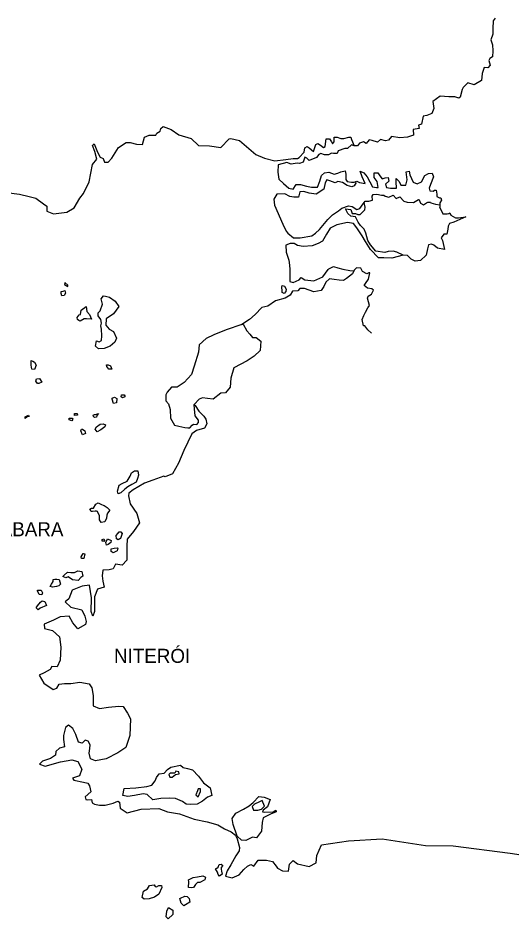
# Model space of a CAD drawing. Extents: x 662444 to 1640468, y 7452018 to 9606170.
# Drawn here: x 690454 to 712609, y 7455211 to 7495631 of the extents above; entities that cross this region are included whole.
import ezdxf

# ---------------------------------------------------------------- set-up
doc = ezdxf.new("R2010")
doc.units = 0
doc.layers.add('Level 1', color=7, linetype='Continuous')
doc.layers.add('Level 3', color=7, linetype='Continuous')

msp = doc.modelspace()

# ---------------------------------------------------------------- linework, layer by layer
at = {"layer": 'Level 1'}
for points in [[(711848, 7495631), (711764, 7495510), (711749, 7495167), (711746, 7494902), (711660, 7494648), (711729, 7494425), (711756, 7494159), (711732, 7493894), (711618, 7493818), (711565, 7493730), (711624, 7493519), (711529, 7493398), (711355, 7493412), (711279, 7493136), (711244, 7492826), (710912, 7492631), (710626, 7492724), (710417, 7492516), (710375, 7492428), (710278, 7492086), (710226, 7492031), (710052, 7492089), (709784, 7492093), (709384, 7492132), (709052, 7491892), (709109, 7491570), (709013, 7491350), (708786, 7491265), (708621, 7491223), (708544, 7490869), (708420, 7490827), (708439, 7490682), (708181, 7490631), (708198, 7490376), (707930, 7490291), (707580, 7490251), (707200, 7490323), (707065, 7490158), (706941, 7490116), (706705, 7490174), (706570, 7490065), (706345, 7490135), (706201, 7490170), (706076, 7489995), (705943, 7490074), (705768, 7490021), (705684, 7489900), (705530, 7489891), (705407, 7489948), (705230, 7489773), (705107, 7489775), (704817, 7489679), (704764, 7489558), (704610, 7489560), (704518, 7489561), (704383, 7489497), (704198, 7489499), (704035, 7489557), (703952, 7489514), (703837, 7489371), (703506, 7489243), (703405, 7489344), (703313, 7489389), (703248, 7489157), (703073, 7489104), (702980, 7489117)], [(689932, 7487801), (690527, 7487727), (690958, 7487622), (691255, 7487552), (691591, 7487293), (691744, 7487191), (691751, 7486969), (692047, 7486844), (692644, 7486925), (692976, 7487109), (693228, 7487549), (693395, 7487757), (693648, 7488286), (693802, 7489059), (693990, 7489300), (693902, 7489645), (693792, 7489912), (693875, 7489988), (694025, 7489610), (694135, 7489387), (694268, 7489330), (694338, 7489163), (694492, 7489161), (694659, 7489347), (694963, 7489819), (695305, 7490048), (695490, 7490045), (695766, 7489975), (696033, 7489961), (696120, 7490292), (696337, 7490378), (696635, 7490374), (696687, 7490462), (696833, 7490560), (696855, 7490670), (696958, 7490757), (697327, 7490631), (697663, 7490394), (698226, 7490220), (698551, 7489906), (699044, 7489900), (699557, 7489826), (699922, 7490209), (699994, 7490219), (700383, 7490137), (701125, 7489507), (701514, 7489347), (701975, 7489219), (702469, 7489279), (702798, 7489330), (702983, 7489327)], [(702983, 7489327), (703066, 7489381), (703285, 7489611), (703319, 7489810), (703422, 7489864), (703514, 7489807), (703707, 7489639), (703814, 7489958), (703907, 7490002), (704019, 7489934), (704151, 7489821), (704234, 7489864), (704270, 7490218), (704321, 7490218), (704424, 7490216), (704515, 7490082), (704554, 7489982), (704638, 7490080), (704641, 7490291), (704774, 7490289), (704938, 7490220), (705071, 7490219), (705288, 7490282), (705381, 7490281), (705410, 7490181), (705530, 7489891)], [(702980, 7489117), (702702, 7489076), (702508, 7489156), (702116, 7489040), (702102, 7488719), (702159, 7488397), (702362, 7488206), (702606, 7487992)], [(702606, 7487992), (702801, 7487956), (702927, 7488165), (703122, 7488162), (703398, 7488092), (703624, 7488045), (703891, 7488041), (703987, 7488306), (704062, 7488560), (704198, 7488691), (704393, 7488721), (704639, 7488629), (704804, 7488671), (704938, 7488736), (705124, 7488778), (705163, 7488633), (705160, 7488390), (705220, 7488300), (705405, 7488265), (705538, 7488263), (705652, 7488306), (705764, 7488249), (706021, 7488201), (705891, 7488513), (705802, 7488758), (705966, 7488689), (706117, 7488510), (706227, 7488287), (706358, 7488063), (706532, 7488028), (706614, 7488027), (706556, 7488304), (706425, 7488483), (706428, 7488683), (706592, 7488681), (706683, 7488546), (706794, 7488423), (706928, 7488454), (707052, 7488475), (707081, 7488308), (706935, 7488177), (706984, 7488033), (707159, 7487997), (707426, 7488005), (707419, 7488282), (707421, 7488426), (707553, 7488302), (707623, 7488135), (707849, 7488132), (707914, 7488375), (707867, 7488730), (707991, 7488761), (708030, 7488595), (708180, 7488260), (708353, 7488191), (708550, 7488277), (708698, 7488563), (708863, 7488650), (709028, 7488669), (709087, 7488503), (708959, 7488161), (708895, 7487996), (708925, 7487873), (709079, 7487860), (709141, 7487915), (709213, 7487914), (709241, 7487736), (709240, 7487625), (709352, 7487568), (709414, 7487568), (709443, 7487456), (709380, 7487335), (709379, 7487247), (709377, 7487114), (709377, 7487125), (709507, 7486846), (709702, 7486844), (709774, 7486865), (709816, 7486897), (709865, 7486786), (710080, 7486672), (710203, 7486671), (710532, 7486710)], [(705620, 7488251), (705536, 7488108), (705423, 7488065), (705218, 7488123), (705004, 7488248), (704799, 7488295), (704685, 7488241), (704440, 7488322), (704307, 7488368), (704233, 7488236), (704167, 7487960), (703825, 7487732), (703517, 7487769), (703272, 7487850), (703097, 7487830), (703032, 7487599), (702830, 7487594), (702652, 7487626)], [(702652, 7487626), (702428, 7487740), (702058, 7487722), (701921, 7487503), (701959, 7487236), (702327, 7486378), (702488, 7486066), (702558, 7485977), (702812, 7485763)], [(702812, 7485763), (702792, 7485774), (703111, 7485770), (703636, 7485852), (703792, 7485982), (703979, 7486146), (704344, 7486595), (704563, 7486803), (704822, 7486988), (704978, 7487107), (705277, 7487203), (705441, 7487168), (705645, 7487043), (705790, 7487085), (705863, 7487195), (705978, 7487349), (706031, 7487414), (706195, 7487412), (706350, 7487454), (706332, 7487643), (706384, 7487720), (706549, 7487729), (706764, 7487681), (706856, 7487691), (706928, 7487635), (707081, 7487599), (707278, 7487685), (707420, 7487539), (707575, 7487604), (707757, 7487413), (707911, 7487367), (708188, 7487352), (708416, 7487482), (708446, 7487470), (708506, 7487325), (708639, 7487257), (708774, 7487344), (708835, 7487365), (708948, 7487364), (708969, 7487341), (709173, 7487283), (709379, 7487247)], [(710532, 7486710), (709995, 7486474), (709809, 7486410), (709746, 7486289), (709733, 7486156), (709689, 7485935), (709556, 7485937), (709430, 7485773), (709500, 7485650), (709587, 7485239), (709270, 7485299), (709097, 7485434), (709005, 7485480), (708871, 7485459), (708827, 7485283), (708762, 7484996), (708502, 7484756), (708265, 7484726), (708092, 7484817), (707919, 7484974), (707724, 7484999), (707438, 7485125), (707274, 7485171), (707058, 7485152), (706904, 7485110), (706504, 7485170), (706261, 7485462), (706140, 7485652), (706052, 7485985), (705973, 7486163), (705820, 7486321), (705710, 7486477), (705589, 7486711), (705374, 7486736), (705242, 7486860), (705142, 7487072), (705378, 7487035), (705448, 7486868), (705592, 7486866), (705694, 7486821), (705807, 7486819), (706015, 7487027), (706017, 7487149), (705978, 7487349)], [(707724, 7484999), (707219, 7484862), (706859, 7484867), (706623, 7484870), (706258, 7485251), (706037, 7485609), (705896, 7485854), (705836, 7485944), (705644, 7486212), (705503, 7486413), (705237, 7486461), (704752, 7486346), (704452, 7486206), (704284, 7485931), (704105, 7485624), (703909, 7485516), (703650, 7485408), (703239, 7485381), (702983, 7485428), (702840, 7485519)], [(702840, 7485519), (702655, 7485510), (702469, 7485435), (702485, 7485125), (702604, 7484769), (702632, 7484547), (702639, 7484347), (702646, 7484059), (702644, 7483937), (702643, 7483805), (702796, 7483769)], [(706310, 7481496), (706148, 7481642), (706006, 7481821), (705945, 7481822), (705887, 7482111), (705971, 7482287), (706035, 7482430), (706140, 7482628), (706224, 7482737), (706126, 7483060), (706158, 7483148), (706313, 7483246), (706398, 7483422), (706327, 7483478), (706122, 7483514), (705979, 7483627), (706032, 7483726), (706168, 7483912), (706234, 7484199), (706193, 7484200), (706099, 7484157), (705906, 7484259), (705826, 7484415), (705641, 7484418), (705537, 7484320), (705452, 7484155), (705192, 7483948), (705058, 7483861), (704852, 7483864), (704637, 7483900), (704432, 7483936), (704255, 7483783), (704170, 7483585), (704055, 7483409), (703715, 7483347), (703296, 7483497), (703091, 7483500), (702997, 7483390), (702770, 7483371)], [(702796, 7483769), (703065, 7483888), (703159, 7483986), (703322, 7483884), (703722, 7483846), (704125, 7484017), (704366, 7484346), (704397, 7484379), (704604, 7484476), (704798, 7484429), (705024, 7484371), (705341, 7484300), (705495, 7484287)], [(692695, 7483646), (692553, 7483769), (692532, 7483681), (692695, 7483590), (692695, 7483646)], [(702290, 7483566), (702301, 7483632), (702403, 7483597), (702474, 7483463), (702472, 7483364), (702389, 7483276), (702297, 7483322), (702298, 7483377), (702290, 7483566)], [(702770, 7483371), (702655, 7483195), (702437, 7483065), (702004, 7482938), (701652, 7482710), (701394, 7482647), (701092, 7482330), (700832, 7482112), (700490, 7481884), (699789, 7481649), (699231, 7481424), (698900, 7481251), (698578, 7480967), (698543, 7480647), (698360, 7480018), (698242, 7479642), (697909, 7479281), (697588, 7479075), (697341, 7479067), (697143, 7478848), (697080, 7478727), (697077, 7478461), (697198, 7478316), (697277, 7478071), (697292, 7477672), (697473, 7477371), (697668, 7477313), (697934, 7477254), (698067, 7477241), (698160, 7477251), (698264, 7477361), (698326, 7477404), (698470, 7477402), (698553, 7477490), (698554, 7477589), (698403, 7477791), (698366, 7478101), (698357, 7478291), (698401, 7478243), (698560, 7477988), (698793, 7477774), (698873, 7477641), (698922, 7477418), (698817, 7477231), (698456, 7477125), (698249, 7476973), (697890, 7476225), (697646, 7475663), (697383, 7475179), (697053, 7475050), (696992, 7475073), (696507, 7474902), (696125, 7474763), (695618, 7474460), (695421, 7474318), (695409, 7474197), (695487, 7473841), (695779, 7473405), (695907, 7472983), (695635, 7472599), (695343, 7472248), (695339, 7471938), (695331, 7471307), (695123, 7471088), (694826, 7471136), (694720, 7470916), (694535, 7470874), (694258, 7470855), (694224, 7470612), (694262, 7470368), (694320, 7470101), (694021, 7470006), (693883, 7469664), (693878, 7469243), (693885, 7468999), (693810, 7468801), (693741, 7469012), (693749, 7469621), (693664, 7470187), (693325, 7470147), (692881, 7469965), (692732, 7469568), (692566, 7469437), (692820, 7469201), (693321, 7469073), (693451, 7468794), (693509, 7468550), (693487, 7468417), (693136, 7468234), (692913, 7468491), (692753, 7468792), (692342, 7468764), (692043, 7468624), (691620, 7468441), (691648, 7468242), (692006, 7468148), (692321, 7467867), (692376, 7467402), (692348, 7466826), (692211, 7466529), (691975, 7466532)], [(692549, 7483404), (692578, 7483282), (692525, 7483183), (692422, 7483162), (692383, 7483273), (692383, 7483340), (692384, 7483362), (692486, 7483372), (692549, 7483404)], [(694201, 7481666), (694172, 7481822), (694204, 7481943), (694165, 7482110), (694044, 7482277), (694046, 7482410), (694140, 7482498), (694246, 7482795), (694188, 7483040), (694282, 7483160), (694384, 7483148), (694558, 7483113), (694813, 7482932), (694974, 7482686), (694734, 7482357), (694402, 7482140), (694398, 7481852), (694540, 7481673), (694734, 7481560), (694874, 7481270), (694799, 7481083), (694592, 7480908), (694323, 7480801), (694066, 7480793), (693924, 7480906), (693968, 7481149), (694101, 7481103), (694205, 7481168), (694207, 7481367), (694201, 7481666)], [(693150, 7482256), (693192, 7482310), (693254, 7482332), (693287, 7482531), (693505, 7482683), (693543, 7482472), (693655, 7482327), (693745, 7482126), (693519, 7482140), (693416, 7482141), (693240, 7482033), (693179, 7482056), (693118, 7482112), (693109, 7482201), (693150, 7482256)], [(700490, 7481884), (700552, 7481894), (700713, 7481593), (700855, 7481447), (700976, 7481301), (701140, 7481299), (701344, 7481141), (701317, 7480710), (701047, 7480459), (700736, 7480252), (700136, 7479939), (699996, 7479476), (699971, 7479077), (699762, 7478814), (699546, 7478806), (699204, 7478533), (698947, 7478559), (698732, 7478584), (698577, 7478531), (698357, 7478291)], [(691048, 7480056), (691040, 7480266), (691112, 7480243), (691193, 7480187), (691263, 7480053), (691199, 7479855), (691076, 7479878), (691048, 7480056)], [(694601, 7480033), (694661, 7479877), (694527, 7479879), (694436, 7479991), (694427, 7480068), (694499, 7480079), (694601, 7480033)], [(691276, 7479444), (691420, 7479464), (691521, 7479297), (691386, 7479232), (691325, 7479233), (691254, 7479333), (691276, 7479444)], [(694878, 7478368), (694744, 7478337), (694674, 7478537), (694675, 7478581), (694788, 7478624), (694890, 7478556), (694878, 7478368)], [(695251, 7478629), (695147, 7478586), (695087, 7478642), (695088, 7478731), (695211, 7478729), (695251, 7478684), (695251, 7478629)], [(690947, 7477753), (690865, 7477743), (690781, 7477667), (690782, 7477744), (690917, 7477809), (690947, 7477753)], [(693125, 7477814), (692991, 7477805), (692982, 7477894), (692992, 7477894), (693105, 7477892), (693125, 7477814)], [(693987, 7477792), (693976, 7477726), (693883, 7477705), (693843, 7477761), (693823, 7477817), (693885, 7477849), (693936, 7477848), (694070, 7477891), (693987, 7477792)], [(692907, 7477629), (692875, 7477552), (692742, 7477598), (692743, 7477675), (692805, 7477686), (692877, 7477685), (692907, 7477629)], [(694350, 7477289), (694174, 7477159), (694009, 7477072), (693907, 7477184), (693970, 7477283), (694136, 7477403), (694280, 7477423), (694372, 7477378), (694350, 7477289)], [(693353, 7477180), (693444, 7477113), (693484, 7476990), (693339, 7476926), (693270, 7477115), (693301, 7477181), (693353, 7477180)], [(695809, 7474967), (695756, 7474812), (695560, 7474704), (695373, 7474596), (695249, 7474487), (695072, 7474323), (694948, 7474280), (694919, 7474402), (694994, 7474667), (695129, 7474743), (695356, 7474851), (695482, 7475071), (695546, 7475225), (695680, 7475323), (695824, 7475321), (695852, 7475121), (695809, 7474967)], [(694275, 7473779), (694315, 7473768), (694458, 7473666), (694569, 7473554), (694475, 7473422), (694443, 7473323), (694421, 7473190), (694347, 7473025), (694182, 7473005), (694112, 7473117), (694114, 7473294), (694024, 7473494), (693973, 7473506), (693912, 7473507), (693788, 7473497), (693737, 7473487), (693677, 7473599), (693749, 7473642), (693842, 7473641), (693947, 7473828), (694050, 7473882), (694193, 7473813), (694275, 7473779)], [(695025, 7472263), (694942, 7472220), (694871, 7472265), (694863, 7472420), (694925, 7472508), (694998, 7472574), (695060, 7472573), (695131, 7472506), (695046, 7472274), (695025, 7472263)], [(694305, 7472151), (694274, 7472162), (694233, 7472163), (694234, 7472240), (694296, 7472273), (694326, 7472184), (694305, 7472151)], [(694612, 7472102), (694498, 7472015), (694426, 7471983), (694397, 7472094), (694471, 7472270), (694634, 7472191), (694612, 7472102)], [(694895, 7471722), (694729, 7471636), (694628, 7471703), (694639, 7471814), (694773, 7471846), (694897, 7471855), (694927, 7471844), (694895, 7471722)], [(693402, 7471376), (693371, 7471376), (693299, 7471377), (693290, 7471455), (693374, 7471609), (693395, 7471609), (693446, 7471586), (693402, 7471376)], [(693268, 7470536), (693153, 7470393), (692897, 7470419), (692704, 7470565), (692601, 7470522), (692468, 7470579), (692520, 7470634), (692676, 7470765), (692829, 7470752), (692994, 7470761), (693138, 7470825), (693323, 7470801), (693361, 7470590), (693268, 7470536)], [(692278, 7470161), (692185, 7470129), (692000, 7470098), (691898, 7470132), (691961, 7470231), (692034, 7470352), (692035, 7470441), (692107, 7470462), (692199, 7470450), (692302, 7470448), (692361, 7470226), (692278, 7470161)], [(691523, 7469760), (691400, 7469762), (691331, 7469929), (691331, 7469962), (691495, 7469960), (691555, 7469838), (691523, 7469760)], [(691458, 7469418), (691530, 7469484), (691663, 7469460), (691733, 7469282), (691454, 7469152), (691351, 7469087), (691270, 7469177), (691322, 7469265), (691458, 7469418)], [(691975, 7466532), (691902, 7466400), (691633, 7466259), (691396, 7466151), (691606, 7465783), (692024, 7465501), (692189, 7465565), (692293, 7465741), (692540, 7465782), (692817, 7465779), (693228, 7465829), (693648, 7465757), (693759, 7465578), (693826, 7465234), (693820, 7464780), (694106, 7464655), (694517, 7464716), (694980, 7464765), (695174, 7464741), (695365, 7464439), (695495, 7464194), (695475, 7463441), (695294, 7462911), (694932, 7462661), (694405, 7462391), (693932, 7462309), (693707, 7462389), (693639, 7462645), (693673, 7462866), (693695, 7463021), (693605, 7463188), (693472, 7463234), (693337, 7463103), (693163, 7463138), (693044, 7463483), (692914, 7463751), (692722, 7463908), (692587, 7463799), (692490, 7463435), (692488, 7463269), (692535, 7462936), (692308, 7462872), (692152, 7462719), (692140, 7462564), (691912, 7462412), (691552, 7462284), (691417, 7462153), (691672, 7462061), (692362, 7462262), (692866, 7462345), (693142, 7462275), (693322, 7461929), (693205, 7461631), (692896, 7461525), (692957, 7461435), (693397, 7461352), (693581, 7461305), (693661, 7461183), (693719, 7460916), (693460, 7460698), (693489, 7460576), (693592, 7460563), (693756, 7460572), (693775, 7460428), (693887, 7460360), (694112, 7460324), (694358, 7460321), (694718, 7460405), (694924, 7460502), (695006, 7460456), (695033, 7460179), (695348, 7459976), (695976, 7460134), (696766, 7460168), (697165, 7460018), (697697, 7459923), (698360, 7459692), (698933, 7459563), (699414, 7459435), (699719, 7459254), (700015, 7459128), (700207, 7458970), (700277, 7458803), (700385, 7458414), (700373, 7458270), (700216, 7458051), (699995, 7457644), (699837, 7457369), (699762, 7457126), (700059, 7457056), (700368, 7457196), (700577, 7457426), (700743, 7457579), (700898, 7457654), (701030, 7457586), (701228, 7457849), (701598, 7457844), (701874, 7457785), (702025, 7457583), (702085, 7457494), (702319, 7457369)], [(697511, 7460623), (697244, 7460626), (696865, 7460609), (696505, 7460559), (696241, 7460795), (696067, 7460819), (695677, 7460758), (695378, 7460706), (695153, 7460753), (695219, 7461063), (695742, 7461089), (696236, 7461149), (696452, 7461213), (696608, 7461410), (696672, 7461564), (696787, 7461718), (697013, 7461759), (697159, 7461924), (697314, 7462021), (697746, 7462104), (697857, 7462003), (698052, 7461967), (698287, 7461909), (698550, 7461617), (698772, 7461315), (699076, 7461090), (699154, 7460745), (698958, 7460670), (698730, 7460496), (698492, 7460355), (698205, 7460348), (698000, 7460362), (697837, 7460475), (697511, 7460623)], [(697537, 7461841), (697485, 7461753), (697280, 7461756), (697217, 7461690), (697257, 7461568), (697369, 7461566), (697515, 7461697), (697689, 7461717), (697670, 7461806), (697537, 7461841)], [(698510, 7460953), (698436, 7460777), (698538, 7460698), (698643, 7460929), (698645, 7461051), (698532, 7461053), (698510, 7460953)], [(700666, 7458732), (700471, 7458745), (700289, 7458925), (700111, 7459448), (700053, 7459714), (700221, 7459956), (700562, 7460140), (700820, 7460280), (700996, 7460444), (701256, 7460706), (701492, 7460670), (701757, 7460578), (701650, 7460236), (701443, 7460095), (701422, 7460017), (701493, 7460005), (701904, 7460022), (702017, 7460087), (702037, 7460020), (701779, 7459913), (701449, 7459751), (701405, 7459541), (701379, 7459154), (701149, 7458847), (700965, 7458883), (700666, 7458732)], [(701217, 7460098), (701382, 7460140), (701507, 7460271), (701398, 7460527), (701284, 7460473), (701057, 7460355), (700963, 7460256), (701022, 7460089), (701217, 7460098)], [(702319, 7457369), (702586, 7457354), (702631, 7457664), (702798, 7457839), (702990, 7457692), (703512, 7457563), (703832, 7457736), (703857, 7458057), (704069, 7458542), (705281, 7458714), (706780, 7458804), (708735, 7458500), (709976, 7458494), (712526, 7458170), (713222, 7458060)], [(699429, 7457541), (699482, 7457651), (699565, 7457672), (699635, 7457604), (699573, 7457517), (699561, 7457439), (699581, 7457350), (699610, 7457217), (699496, 7457130), (699425, 7457208), (699406, 7457308), (699315, 7457454), (699367, 7457486), (699429, 7457541)], [(698316, 7457079), (698511, 7457099), (698747, 7457151), (698870, 7457094), (698827, 7456962), (698610, 7456843), (698497, 7456844), (698414, 7456757), (698330, 7456625), (698228, 7456615), (698105, 7456628), (698108, 7456871), (698099, 7456971), (698316, 7457079)], [(696334, 7456119), (696118, 7456100), (696017, 7456179), (696082, 7456455), (696268, 7456563), (696352, 7456706), (696568, 7456748), (696608, 7456669), (696669, 7456647), (696773, 7456712), (696885, 7456710), (696905, 7456621), (696767, 7456324), (696581, 7456182), (696334, 7456119)], [(697935, 7456231), (698038, 7456219), (698129, 7456129), (698157, 7455962), (697971, 7455843), (697889, 7455800), (697777, 7455923), (697708, 7456123), (697739, 7456145), (697935, 7456231)], [(697391, 7455408), (697194, 7455211), (697103, 7455312), (697127, 7455555), (697201, 7455731), (697394, 7455607), (697393, 7455518), (697391, 7455408)]]:
    msp.add_lwpolyline(points, dxfattribs=at)

# ---------------------------------------------------------------- texts
at = {"layer": 'Level 3'}
for s, height, p in [('BAIA DE GUANABARA', 630.04, (683642, 7472381)), ('NITERÓI', 629.8, (694761, 7466701))]:
    msp.add_text(s, height=height, dxfattribs=at).set_placement(p)

doc.saveas('drawing.dxf')
